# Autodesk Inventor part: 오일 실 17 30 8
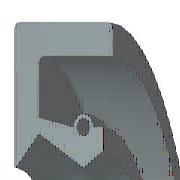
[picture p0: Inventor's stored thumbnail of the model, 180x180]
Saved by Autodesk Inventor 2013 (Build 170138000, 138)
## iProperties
IsCustomPart: 1
Created: 2012-02
Part Number: 오일 실 17 30 8
Material: 고무
Description: 오일-실
Document SubType Name: Modeling
Standard: KS B 2804
Designer: mduedu
Standards Organization: KS
Language: ko-KR
Size Designation: D - 17 30 8
Categories: <MemberInstance><Categories><Category DisplayName="샤프트 부품" InternalName="7f7aeb1f-a693-4053-b835-cee3144e0d98" Mnemonic="SHFT"><Category DisplayName="실링" Intern
Density: 0.93 g/cm^3
Author: mduedu
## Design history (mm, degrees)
revolve "본체" stored, may be unused: angle "d17" = 90 deg
revolve "스프링1" stored, may be unused: angle "d18" = 90 deg
body "Solid1"
sketch "스케치1"
  geometry: L1 (0, 15)-(8, 15); L2 (8, 13.25)-(1.75, 13.25); L3 (1.75, 10.25)-(4.9, 8.5); L4 (4.9, 8.5)-(0, 8.5); L5 (0, 0)-(9.586, 0) reference; L6 (4.9, 8.5)-(6.3, 9.375); L7 (0, 18)-(0, -3) reference; L8 (-1.941, 0)-(11.507, 0) reference; L9 (4.2, 10.6)-(1.75, 11.21); L10 (1.75, 11.21)-(1.75, 13.25); L11 (0, 15)-(0, 8.588); L12 (4.9, 8.5)-(0, 8.5); L13 (1.75, 10.25)-(0.152, 8.528); L14 (8, 15)-(8, 13.25); L15 (5.6, 10.6)-(6.3, 10.6); L16 (6.3, 10.6)-(6.3, 9.375); C1 r 0.455 at (4.9, 10.6); A1 r 0.7 centre (4.9, 10.6) between (5.6, 10.6) and (4.2, 10.6); A2 r 0.088 centre (0.088, 8.588) between (0, 8.588) and (0.152, 8.528); 1 further point
  constraints: 28 end point, 5 horizontal alignment, 5 point on line, 4 point on circle, 4 vertical alignment, 3 centre point, 3 tangent, 2 collinear, 2 horizontal, 2 perpendicular, 1 coincident, 1 parallel
  dimensions: "d0" = 30 diameter of L1 L5 (= SD2); "d1" = 1.75 distance of L1.end L2.start (= SD); "d2" = 0.91 diameter of C1 (= SPDI); "d3" = 1.4 diameter of A1 (= SPDA); "d4" = 17 diameter of L3.end L5 (= NND); "d5" = 20.5 diameter of L3.start L5 (= TKDM); "d7" = 22.42 diameter of L9.end L5 (= TKDM + 0.24 x SWDT); "d8" = 1.75 distance between parallel lines of L11 L10 (= SD); "d9" = 4.9 distance from line of L11 C1.centre (= SPDST); "d10" = 21.2 diameter of C1.centre L5 (= HLDM); "d11" = 0.0875 radius of A2 (= 0.25 x LAB); "d12" = 6.3 distance between parallel lines of L11 L16 (= SDI); "d13" = 18.75 diameter of L6.end L5 (= ABDM); "d14" = 8 distance from line of L11 L1.end (= SWDT)
fillet "모깎기1" dims "d6" = 0.3 (= RR)
other parameters: "SD2" = 30 [user parameter; used in 1 equation term], "SWDT" = 8 [user parameter; used in 2 equation terms], "RR" = 0.3 [user parameter; used in 1 equation term], "SD" = 1.75 [user parameter; used in 2 equation terms], "NND" = 17 [user parameter; used in 1 equation term], "SPDA" = 1.4 [user parameter; used in 1 equation term], "SPDI" = 0.91 [user parameter; used in 1 equation term], "TKDM" = 20.5 [user parameter; used in 2 equation terms], "HLDM" = 21.2 [user parameter; used in 1 equation term], "ABDM" = 18.75 [user parameter; used in 1 equation term], "SDI" = 6.3 [user parameter; used in 1 equation term], "SPDST" = 4.9 [user parameter; used in 1 equation term], "LAB" = 0.35 [user parameter; used in 1 equation term], "d15" = 0, "d16" = 0, "d19" = 0
